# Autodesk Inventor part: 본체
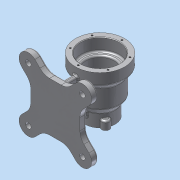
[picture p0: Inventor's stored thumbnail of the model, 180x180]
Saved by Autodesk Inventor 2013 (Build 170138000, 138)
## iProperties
Created: 2017-03
Part Number: 본체
Material: 알루미늄 6061
Document SubType Name: Modeling
Designer: dgall
Density: 2.71 g/cm^3
Mass: 1008.04 g
Surface Area: 842.102 cm^2
Volume: 371.972 cm^3
Author: dgall
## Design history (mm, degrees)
sketch "스케치1"
  geometry: L1 (0, 50)-(0, -50); L2 (35, 50)-(35, 27); L3 (35, 27)-(26, 27); L4 (26, 27)-(26, -20); L5 (26, -20)-(17.5, -20); L6 (17.5, -20)-(17.5, -50); L7 (17.5, -50)-(27.5, -50); L8 (27.5, -50)-(27.5, -27); L9 (27.5, -27)-(36, -15); L10 (36, -15)-(36, 19); L11 (36, 19)-(45, 30); L12 (45, 30)-(45, 50); L13 (45, 50)-(35, 50); 2 further points
  constraints: 26 end point, 9 parallel, 2 horizontal alignment, 1 coincident, 1 midpoint, 1 perpendicular, 1 vertical
  dimensions: "d0" = 100 distance of L1.start L1.end; "d1" = 23 distance of L2.start L2.end; "d2" = 47 distance of L3.end L4.end; "d3" = 20 distance of L11.end L12.end; "d4" = 31 vertical distance of L10.end L12.end; "d5" = 65 distance from line of L13 L9.end; "d6" = 23 distance of L7.end L8.end; "d7" = 90 diameter of L12 L1; "d8" = 72 diameter of L10 L1; "d9" = 55 diameter of L8 L1; "d10" = 52 diameter of L4 L1; "d11" = 70 diameter of L2 L1; "d12" = 35 diameter of L6 L1
revolve "회전1" sketch "스케치1" stored, may be unused: angle "d13" = 90 deg
sketch "스케치2"
  geometry: C1 r 45 at (0, 0) reference; 1 further point
  constraints: 1 vertical alignment
  dimensions: "d15" = 40 distance of C1.centre point (0, 40)
hole "구멍1" sketch "스케치2" at (0, 40) diameter "d16" = 3.242; stored, may be unused: countersink angle "d20" = 90 deg, drill point angle "d22" = 118 deg; dims "d17" = 9, "d18" = 4, "d19" = 2, "d21" = 11
sketch "스케치3"
  geometry: C1 r 7 at (0, 27.5); 1 further point
  constraints: 1 centre point, 1 vertical alignment, 1 other
  dimensions: "d26" = 14 diameter of C1
extrude "돌출1" join sketch "스케치3" distance "d27" = 15; taper "d28" = 0 deg
hole "구멍2" diameter "d31" = 3.242; stored, may be unused: countersink angle "d35" = 90 deg, drill point angle "d37" = 118 deg; dims "d29" = 10, "d30" = 10, "d32" = 9, "d33" = 4, "d34" = 2, "d36" = 11
node "작업 평면1"
sketch "스케치4"
  geometry: L1 (-45, 50)-(45, 50) reference; C1 r 5 at (0, 0); 1 further point
  constraints: 1 centre point, 1 midpoint, 1 vertical alignment
  dimensions: "d42" = 10 diameter of C1; "d43" = 50 distance from line of L1 C1.centre
extrude "돌출2" join sketch "스케치4" stored distance "d44" = 15; taper "d45" = 0 deg
node "작업 평면2"
sketch "스케치5"
  geometry: L1 (-45, 45)-(45, 45); L2 (45, 45)-(45, -45); L3 (45, -45)-(-45, -45); L4 (-45, -45)-(-45, 45); 3 further points
  constraints: 8 end point, 2 midpoint, 2 parallel, 2 perpendicular, 1 horizontal, 1 horizontal alignment, 1 vertical alignment
  dimensions: "d47" = 90 distance of L1.start L1.end
extrude "돌출3" join sketch "스케치5" distance "d49" = 12; taper "d50" = 0 deg
sketch "스케치6"
  geometry: L1 (-45, -45)-(45, -45) reference; L2 (45, 45)-(-45, 45) reference; L3 (-45, 45)-(-45, -45) reference; L4 (-61.518, 37.477)-(-45, 20.958); L5 (-37.477, 61.518)-(-20.958, 45); L6 (-49.497, 49.497)-(0, 0); C1 r 5 at (-49.497, 49.497); A1 r 70 centre (0, 0) between (-49.497, 49.497) and (-36.106, 59.97); A2 r 17 centre (-49.497, 49.497) between (-36.106, 59.97) and (-59.97, 36.106); 1 further point
  constraints: 7 point on circle, 6 end point, 3 centre point, 2 coincident, 2 parallel, 2 point on line, 2 tangent
  dimensions: "d51" = 140 diameter of A1; "d52" = 34 diameter of A2; "d54" = 10 diameter of C1; "d55" = 45 deg angle of L1 L6
extrude "돌출4" join sketch "스케치6" distance "d56" = 12; taper "d57" = 0 deg
hole "구멍3" diameter "d63" = 4.134; stored, may be unused: countersink angle "d67" = 90 deg, drill point angle "d69" = 118 deg; dims "d61" = 10, "d62" = 10, "d64" = 40, "d65" = 4, "d66" = 2, "d68" = 11
sketch "스케치7"
  geometry: L1 (-70, -20.958)-(-70, 20.958) reference; L2 (-70, 20.958)-(-70, 37.477) reference; L3 (-70, 37.477)-(-70, 66.497) reference; L4 (-70, -37.477)-(-70, -20.958) reference; L5 (-70, -66.497)-(-70, -37.477) reference; L6 (-45, 30)-(45, 30) reference; L7 (-45, 50)-(45, 50) reference; L8 (-45, 50)-(-45, 30) reference; L9 (-36, 19)-(-36, -15) reference; L10 (-45, 30)-(-36, 19) reference; L11 (-36, -15)-(-27.5, -27) reference; L12 (-7.292, -50)-(-7.292, -35) reference; L13 (-7.292, -35)-(-19.317, -35) reference; L14 (-19.317, -35)-(-19.317, -50) reference; L15 (-19.317, -50)-(-19.317, -50) reference; L16 (-19.317, -50)-(-19.317, -35) reference; L17 (-19.317, -35)-(-7.292, -35) reference; L18 (-7.292, -35)-(-7.292, -50) reference; L19 (26.609, -50)-(-7.292, -50) reference; L20 (26.609, -50)-(26.609, -35) reference; L21 (26.609, -35)-(26.609, -35) reference; L22 (26.609, -35)-(26.609, -50) reference; L23 (-7.292, -50)-(26.609, -50) reference; L24 (-27.5, -27)-(27.5, -27) reference; L25 (-27.5, -27)-(-27.5, -50) reference; L26 (-27.5, -37)-(-70, -37); L27 (-45, 37)-(-70, 37); 3 further points
  constraints: 4 end point, 4 point on line, 2 perpendicular
  dimensions: "d70" = 37 distance from line of L27 point (0, 0); "d71" = 37 distance from line of L26 point (0, 0)
  node "투영된 루프1"
  node "투영된 루프2"
feature "리브1" dims "d72" = 37, "d73" = 8, "d74" = 0, "d75" = 0, "d76" = 1, "d77" = 1
feature "리브2" dims "d78" = 37, "d79" = 8, "d80" = 0, "d81" = 0, "d82" = 1, "d83" = 1
sketch "스케치8"
  geometry: L1 (-20.958, -70)-(-37.477, -70) reference; L2 (20.958, -70)-(-20.958, -70) reference; L3 (37.477, -70)-(20.958, -70) reference; L4 (66.497, -70)-(37.477, -70) reference; L5 (-37.477, -70)-(-66.497, -70) reference; L6 (-4, -70)-(-4, -27.208) reference; L7 (4, -27.208)-(4, -70) reference; L8 (-25, -70)-(-18.14, -31.096); A1 r 36 centre (0, 0) between (4, -35.777) and (-4, -35.777) reference; 3 further points
  constraints: 2 end point, 1 point on circle, 1 point on line
  dimensions: "d85" = 25 horizontal distance of point (0, 0) L8.start; "d86" = 100 deg angle of L1 L8
extrude "돌출5" join sketch "스케치8" stored distance "d87" = 8; taper "d88" = 0 deg
fillet "모깎기1" dims "d89" = 25
fillet "모깎기2" dims "d90" = 3
fillet "모깎기3" dims "d91" = 1
chamfer "모따기1" distance "d92" = 1; stored, may be unused: second distance "d93" = 2, angle "d94" = 45 deg
fillet "모깎기4" dims "d95" = 3
fillet "모깎기5" dims "d96" = 3
fillet "모깎기6" dims "d97" = 3
fillet "모깎기7" dims "d98" = 3
fillet "모깎기8" dims "d99" = 3
fillet "모깎기9" dims "d100" = 3
sketch "스케치9"
  geometry: L1 (10.603, 45)-(-10.603, 45) reference; 2 further points
  constraints: 1 other
  dimensions: "d101" = 35 distance of point (0, 0) point (35, 0); "d102" = 45 distance from line of point (35, 0) L1
feature "엠보싱1" sketch "스케치9" dims "d0" = 100, "d1" = 23, "d2" = 47, "d3" = 20, "d4" = 31, "d5" = 65, "d6" = 23, "d7" = 90, "d8" = 72, "d9" = 55, "d10" = 52, "d11" = 70, "d12" = 35, "d15" = 40, "d103" = 0.5, "d104" = 0
node "솔리드1"
pattern_circular "원형 패턴1" dims angle "d24" = 360 deg
pattern_circular "원형 패턴2" dims angle "d39" = 360 deg
pattern_circular "원형 패턴3" dims angle "d59" = 360 deg
mirror "대칭1"
other parameters: "d46" = -82
